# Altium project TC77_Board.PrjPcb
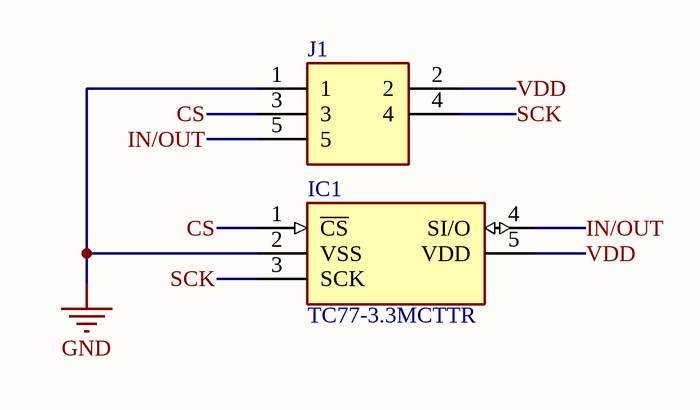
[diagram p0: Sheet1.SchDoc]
1 sheet, 2 parts. Net scope: global (net labels, ports and power ports of the same name join across sheets).
Board file: PCB1.PcbDoc

## Sheet Sheet1.SchDoc
size A3

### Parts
IC1  TC77-3.3MCTTR  [SOT95P280X145-5N]
J1  61000618221_5pins  [61000618221_5pins]  (value not drawn)

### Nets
GND: IC1.2(VSS) J1.1
CS: IC1.1(~{CS}) J1.3
IN/OUT: IC1.4(SI/O) J1.5
SCK: IC1.3(SCK) J1.4
VDD: IC1.5(VDD) J1.2

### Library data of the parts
IC1 = TC77-3.3MCTTR: Integrated Circuit; Manufacturer_Name: Microchip
J1 = 61000618221_5pins: Connector; Manufacturer_Name: Wurth Elektronik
